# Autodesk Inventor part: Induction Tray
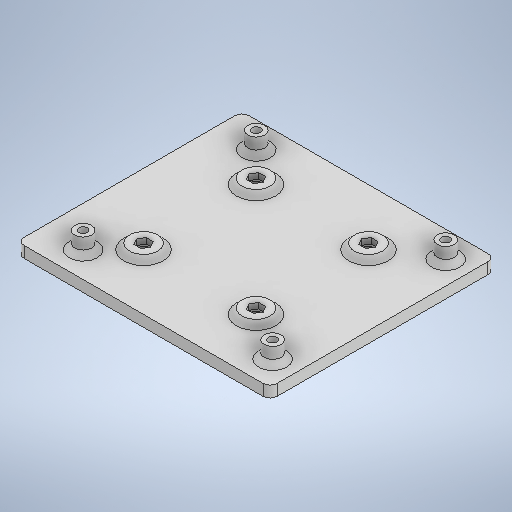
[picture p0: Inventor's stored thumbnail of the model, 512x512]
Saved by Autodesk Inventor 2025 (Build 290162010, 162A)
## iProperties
Created: 2023-12
Part Number: Induction Tray
Material: Generic
Document SubType Name: Modeling
Designer: Andrew
Density: 1 g/cm^3
Appearance: Default
Author: Andrew
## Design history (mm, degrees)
sketch "Sketch1"
  geometry: L1 (57.15, 50.8)-(-57.15, 50.8); L2 (-57.15, 50.8)-(-57.15, -50.8); L3 (-57.15, -50.8)-(57.15, -50.8); L4 (57.15, -50.8)-(57.15, 50.8); 2 further points
  constraints: 8 end point, 2 parallel, 1 horizontal, 1 midpoint, 1 perpendicular
  dimensions: "d0" = 101.6 distance between parallel lines of L3 L1; "d1" = 50.8 distance from line of point (0, 0) L1 (= 0.5 x d0); "d2" = 114.3 distance between parallel lines of L2 L4; "d3" = 57.15 distance of point (0, 0) point (57.15, 0) (= 0.5 x d2)
extrude "Extrusion1" new body sketch "Sketch1" distance "d4" = 5.08; taper "d5" = 0 deg
fillet "Fillet1" dims "d6" = 3.175
sketch "Sketch2"
  geometry: L1 (57.15, -47.625)-(57.15, 47.625) reference; L2 (-57.15, 47.625)-(-57.15, -47.625) reference; L3 (-53.975, -50.8)-(53.975, -50.8) reference; L4 (53.975, 50.8)-(-53.975, 50.8) reference; C1 r 1.905 at (-38.989, 39.116); C2 r 3.81 at (-38.989, 39.116); C3 r 1.905 at (46.609, 39.116); C4 r 3.81 at (46.609, 39.116); C5 r 3.81 at (46.609, -39.116); C6 r 3.81 at (46.609, -39.116); C7 r 1.905 at (-38.989, -39.116); C8 r 3.81 at (-38.989, -39.116); C9 r 1.905 at (46.609, -39.116); 1 further point
  constraints: 9 centre point, 5 coincident, 2 horizontal alignment, 2 vertical alignment
  dimensions: "d7" = 3.81 diameter of C1; "d8" = 3.81 diameter of C3 (= d7); "d9" = 3.81 diameter of C7 (= d8); "d10" = 7.62 diameter of C5; "d11" = 7.62 diameter of C6; "d12" = 7.62 diameter of C8 (= d11); "d13" = 7.62 diameter of C4 (= d11); "d14" = 7.62 diameter of C2 (= d11); "d15" = 93.218 dimension on C4 C2; "d16" = 78.232 distance of C5.centre C3.centre; "d17" = 114.3 distance between parallel lines of L1 L2 (derived); "d18" = 101.6 distance between parallel lines of L3 L4 (derived); "d41" = 11.684 distance from line of C5.centre L3 (= -0.5 x d16 + 0.5 x d18); "d42" = 10.541 distance from line of C3.centre L1 (= -0.5 x d15 + 0.5 x d17); "d43" = 3.81 diameter of C9 (= d7)
extrude "Extrusion2" join sketch "Sketch2" distance "d21" = 7.62; taper "d22" = 0 deg
sketch "Sketch3"
  geometry: L1 (57.15, 47.625)-(57.15, -47.625) reference; L2 (-57.15, -47.625)-(-57.15, 47.625) reference; L3 (53.975, -50.8)-(-53.975, -50.8) reference; L4 (-53.975, 50.8)-(53.975, 50.8) reference; C1 r 1.905 at (-25.4, 25.4); C2 r 3.81 at (-25.4, 25.4); C3 r 1.905 at (25.4, 25.4); C4 r 3.81 at (25.4, 25.4); C5 r 1.905 at (25.4, -25.4); C6 r 3.81 at (25.4, -25.4); C7 r 1.905 at (-25.4, -25.4); C8 r 3.81 at (-25.4, -25.4); 1 further point
  constraints: 8 centre point, 4 coincident, 2 horizontal alignment, 2 vertical alignment
  dimensions: "d23" = 3.81 diameter of C1; "d24" = 3.81 diameter of C3 (= d23); "d25" = 3.81 diameter of C5 (= d23); "d26" = 3.81 diameter of C7 (= d23); "d27" = 7.62 diameter of C2; "d28" = 7.62 diameter of C4 (= d27); "d29" = 7.62 diameter of C6 (= d27); "d30" = 7.62 diameter of C8 (= d27); "d31" = 50.8 distance of C3.centre C1.centre; "d32" = 50.8 distance of C5.centre C3.centre; "d33" = 114.3 distance between parallel lines of L1 L2 (derived); "d34" = 101.6 distance between parallel lines of L3 L4 (derived); "d35" = 31.75 distance from line of L2 C1.centre (= -0.5 x d31 + 0.5 x d33); "d36" = 25.4 distance from line of C5.centre L3 (= -0.5 x d32 + 0.5 x d34)
extrude "Extrusion3" join sketch "Sketch3" distance "d37" = 7.62; taper "d38" = 0 deg
sketch "Sketch4"
  geometry: C1 r 1.905 at (-25.4, 25.4) reference; C2 r 1.905 at (25.4, 25.4) reference; C3 r 1.905 at (-25.4, -25.4) reference; C4 r 1.905 at (25.4, -25.4) reference; C5 r 3.81 at (46.609, 39.116) reference; C6 r 1.905 at (46.609, -39.116) reference; C7 r 1.905 at (-38.989, 39.116) reference; C8 r 1.905 at (-38.989, -39.116) reference; C9 r 3.81 at (46.609, 39.116) reference; C10 r 1.905 at (46.609, 39.116) reference; C11 r 1.905 at (46.609, 39.116) reference; 1 further point
extrude "Extrusion4" cut sketch "Sketch4" distance "d39" = 12.7; taper "d40" = 0 deg
sketch "Sketch5"
  geometry: L1 (-26.984, 28.143)-(-23.816, 28.143); L2 (-23.816, 28.143)-(-22.232, 25.4); L3 (-22.232, 25.4)-(-23.816, 22.657); L4 (-23.816, 22.657)-(-26.984, 22.657); L5 (-26.984, 22.657)-(-28.568, 25.4); L6 (-28.568, 25.4)-(-26.984, 28.143); L7 (23.816, 28.143)-(26.984, 28.143); L8 (26.984, 28.143)-(28.568, 25.4); L9 (28.568, 25.4)-(26.984, 22.657); L10 (26.984, 22.657)-(23.816, 22.657); L11 (23.816, 22.657)-(22.232, 25.4); L12 (22.232, 25.4)-(23.816, 28.143); L13 (-23.816, -22.657)-(-22.232, -25.4); L14 (-22.232, -25.4)-(-23.816, -28.143); L15 (-23.816, -28.143)-(-26.984, -28.143); L16 (-26.984, -28.143)-(-28.568, -25.4); L17 (-28.568, -25.4)-(-26.984, -22.657); L18 (-26.984, -22.657)-(-23.816, -22.657); L19 (26.984, -22.657)-(28.568, -25.4); L20 (28.568, -25.4)-(26.984, -28.143); L21 (26.984, -28.143)-(23.816, -28.143); L22 (23.816, -28.143)-(22.232, -25.4); L23 (22.232, -25.4)-(23.816, -22.657); L24 (23.816, -22.657)-(26.984, -22.657); C1 r 1.905 at (-25.4, 25.4) reference; C2 r 1.905 at (25.4, 25.4) reference; C3 r 6.35 at (-25.4, 25.4); C4 r 6.35 at (25.4, 25.4); C5 r 1.905 at (-25.4, -25.4) reference; C6 r 1.905 at (25.4, -25.4) reference; C7 r 1.905 at (-25.4, -25.4) reference; C8 r 6.35 at (-25.4, -25.4); C9 r 6.35 at (25.4, -25.4); 4 further points
  constraints: 48 end point, 8 coincident, 4 centre point, 4 horizontal, 52 other
  dimensions: "d44" = 5.4864 distance between parallel lines of L3 L6; "d45" = 5.4864 distance between parallel lines of L9 L12 (= d44); "d48" = 12.7 diameter of C3; "d49" = 12.7 diameter of C4 (= d48); "d57" = 5.4864 distance between parallel lines of L15 L18 (= d45); "d58" = 5.4864 distance between parallel lines of L21 L24 (= d45); "d59" = 12.7 diameter of C9 (= d49); "d60" = 12.7 diameter of C8 (= d49)
extrude "Extrusion5" join sketch "Sketch5" distance "d52" = 2.54; taper "d53" = 0 deg
chamfer "Chamfer1" distance "d54" = 2.54; stored, may be unused: second distance "d55" = 3.175, angle "d56" = 45 deg
sketch "Sketch6"
  geometry: L1 (49.329, 37.493)-(46.564, 35.949); L2 (46.564, 35.949)-(43.843, 37.572); L3 (43.843, 37.572)-(43.889, 40.739); L4 (43.889, 40.739)-(46.654, 42.283); L5 (46.654, 42.283)-(49.375, 40.66); L6 (49.375, 40.66)-(49.329, 37.493); L7 (48.193, -41.859)-(45.025, -41.859); L8 (45.025, -41.859)-(43.441, -39.116); L9 (43.441, -39.116)-(45.025, -36.373); L10 (45.025, -36.373)-(48.193, -36.373); L11 (48.193, -36.373)-(49.777, -39.116); L12 (49.777, -39.116)-(48.193, -41.859); L13 (-37.405, -41.859)-(-40.573, -41.859); L14 (-40.573, -41.859)-(-42.157, -39.116); L15 (-42.157, -39.116)-(-40.573, -36.373); L16 (-40.573, -36.373)-(-37.405, -36.373); L17 (-37.405, -36.373)-(-35.821, -39.116); L18 (-35.821, -39.116)-(-37.405, -41.859); L19 (-37.405, 36.373)-(-40.573, 36.373); L20 (-40.573, 36.373)-(-42.157, 39.116); L21 (-42.157, 39.116)-(-40.573, 41.859); L22 (-40.573, 41.859)-(-37.405, 41.859); L23 (-37.405, 41.859)-(-35.821, 39.116); L24 (-35.821, 39.116)-(-37.405, 36.373); C1 r 1.905 at (46.609, 39.116) reference; C2 r 1.905 at (46.609, -39.116) reference; C3 r 1.905 at (-38.989, -39.116) reference; C4 r 1.905 at (-38.989, 39.116) reference; C5 r 6.35 at (46.609, -39.116); C6 r 6.35 at (46.609, 39.116); C7 r 6.35 at (-38.989, 39.116); C8 r 6.35 at (-38.989, -39.116); 6 further points
  constraints: 48 end point, 8 coincident, 4 centre point, 3 horizontal, 1 midpoint, 1 point on line, 52 other
  dimensions: "d61" = 5.4864 distance from line of point (43.866, 39.155) L6; "d62" = 5.4864 distance between parallel lines of L9 L12 (= d61); "d63" = 5.4864 distance between parallel lines of L22 L19 (= d61); "d64" = 5.4864 distance between parallel lines of L16 L13 (= d62); "d65" = 12.7 diameter of C6; "d66" = 12.7 diameter of C5 (= d65); "d67" = 12.7 diameter of C7 (= d65); "d68" = 12.7 diameter of C8 (= d65)
extrude "Extrusion6" join sketch "Sketch6" distance "d69" = 2.54; taper "d70" = 0 deg
chamfer "Chamfer2" distance "d71" = 2.54; stored, may be unused: second distance "d72" = 3.175, angle "d73" = 45 deg
chamfer "Chamfer3" distance "d74" = 2.54; stored, may be unused: second distance "d75" = 3.175, angle "d76" = 45 deg
body "Solid1"
node "Projected Loop1"
node "Projected Loop2"
node "Projected Loop3"
node "Projected Loop4"
node "Projected Loop5"
